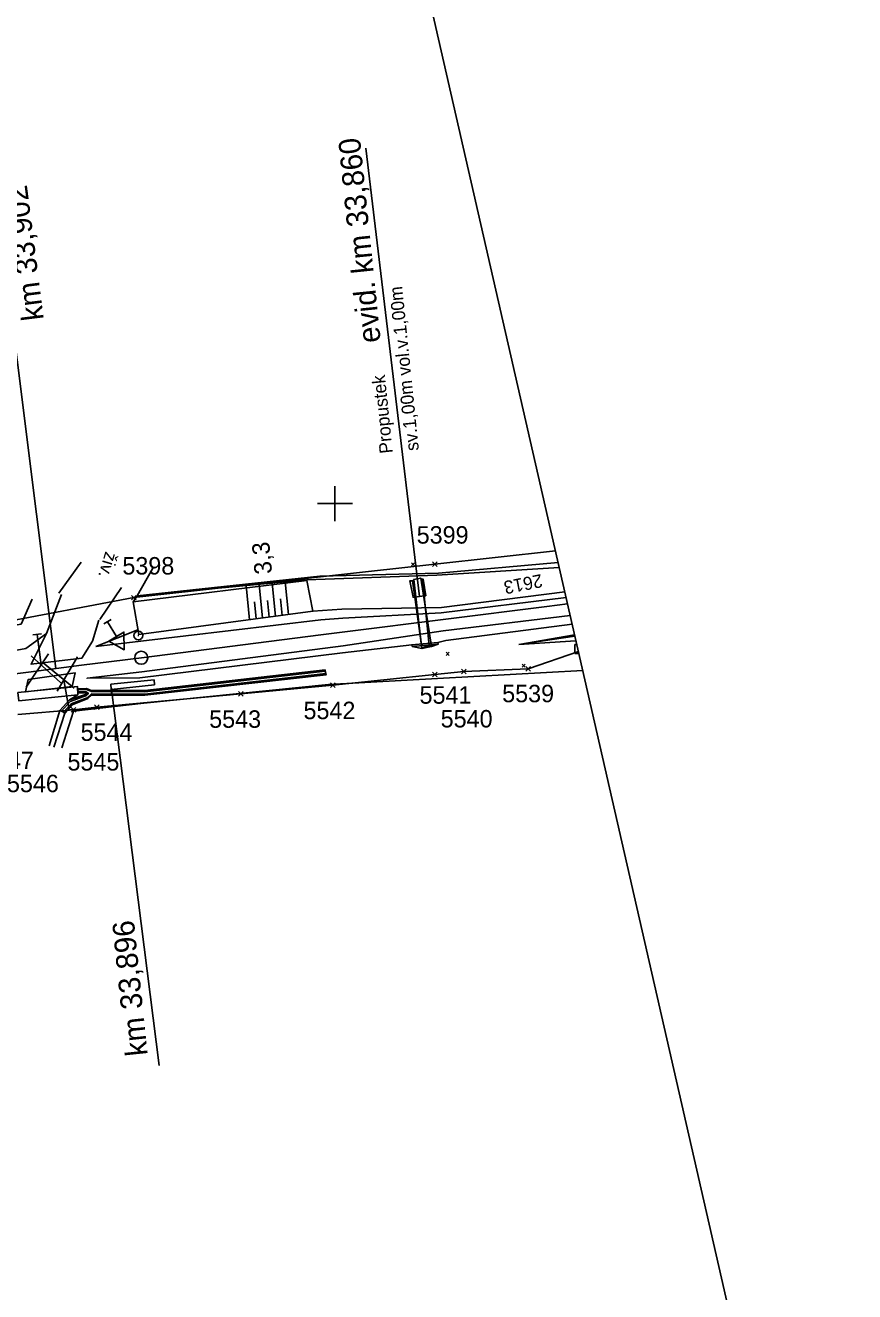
# Model space of a CAD drawing. Extents: x -805730 to -804640, y -1150889 to -1150366.
# Drawn here: x -804735.5 to -804640.4, y -1150590.3 to -1150445.2 of the extents above; entities that cross this region are included whole.
import ezdxf

# ---------------------------------------------------------------- set-up
doc = ezdxf.new("R2010")
doc.units = 0
for name, color, linetype in [('0381KM032-037P - Vrstva 1', 7, 'Continuous'), ('0381KM032-037P - Vrstva 13', 7, 'Continuous'), ('0381KM032-037P - Vrstva 17', 7, 'Continuous'), ('0381KM032-037P - Vrstva 19', 7, 'Continuous'), ('0381KM032-037P - Vrstva 25', 7, 'Continuous'), ('0381KM032-037P - Vrstva 4', 7, 'Continuous'), ('0381KM032-037P - Vrstva 43', 7, 'Continuous'), ('0381KM032-037P - Vrstva 48', 7, 'Continuous'), ('0381KM032-037P - Vrstva 49', 7, 'Continuous'), ('0381KM032-037P - Vrstva 51', 7, 'Continuous'), ('0381KM032-037P - Vrstva 57', 7, 'Continuous'), ('0381KM032-037P - Vrstva 7', 7, 'Continuous'), ('0381KM032-037P - Vrstva 9', 7, 'Continuous'), ('formát', 7, 'Continuous'), ('krizky_1000 - Vrstva 1', 7, 'Continuous'), ('szdc - hran DP', 7, 'Continuous'), ('szdc - szdc_cislo', 7, 'Continuous'), ('szdc - szdc_krizek', 7, 'Continuous')]:
    doc.layers.add(name, color=color, linetype=linetype)

msp = doc.modelspace()

# ---------------------------------------------------------------- linework, layer by layer
at = {"layer": '0381KM032-037P - Vrstva 1'}
msp.add_lwpolyline([(-804673.35, -1150511.49), (-804675.7, -1150511.78), (-804698.85, -1150514.71), (-804701.61, -1150515.06), (-804722.18, -1150517.67), (-804729.05, -1150518.54), (-804735.1, -1150519.31), (-804744.56, -1150520.5), (-804767.65, -1150523.46), (-804791, -1150526.42)], dxfattribs=at)
at = {"layer": '0381KM032-037P - Vrstva 13'}
for points in [[(-804703.22, -1150508.8), (-804723.12, -1150511.26), (-804722.46, -1150514.99), (-804702.53, -1150512.35), (-804703.22, -1150508.8)], [(-804732.2, -1150527.92), (-804730.97, -1150524.01), (-804730.13, -1150523.06), (-804728.33, -1150522.36), (-804727.9, -1150521.95), (-804721.78, -1150521.96), (-804701.01, -1150519.63), (-804701.03, -1150519.46), (-804701.1, -1150519.22), (-804701.1, -1150519.05)], [(-804729.45, -1150521.32), (-804728.46, -1150521.31), (-804727.91, -1150521.54), (-804721.8, -1150521.59), (-804701.1, -1150519.22)], [(-804729.38, -1150521.22), (-804728.48, -1150521.2), (-804727.92, -1150521.41), (-804721.8, -1150521.43), (-804701.1, -1150519.05)], [(-804731.12, -1150523.92), (-804730.21, -1150522.94), (-804728.39, -1150522.25), (-804727.91, -1150521.81), (-804721.79, -1150521.85), (-804701.03, -1150519.46)], [(-804732.74, -1150527.78), (-804731.51, -1150523.73), (-804730.41, -1150522.51), (-804728.49, -1150521.85), (-804728.25, -1150521.76), (-804728.53, -1150521.71), (-804729.44, -1150521.68)], [(-804731.32, -1150523.78), (-804730.35, -1150522.68), (-804728.48, -1150521.99), (-804728.25, -1150521.76), (-804728.5, -1150521.58), (-804729.42, -1150521.57)], [(-804729.38, -1150521.22), (-804729.45, -1150521.32), (-804729.42, -1150521.57), (-804729.44, -1150521.68)], [(-804731.51, -1150523.73), (-804731.32, -1150523.78), (-804731.12, -1150523.92), (-804730.97, -1150524.01)]]:
    msp.add_lwpolyline(points, dxfattribs=at)
at = {"layer": '0381KM032-037P - Vrstva 17'}
for p, q in [((-804731.66, -1150510.27), (-804729.1, -1150506.73)), ((-804726.96, -1150513.28), (-804724.46, -1150509.62))]:
    msp.add_line(p, q, dxfattribs=at)
for points in [[(-804674.43, -1150506.74), (-804688.14, -1150507.97), (-804701.71, -1150508.32), (-804722.68, -1150510.59), (-804720.85, -1150507.4)], [(-804734.71, -1150510.96), (-804735.96, -1150513.84), (-804741.77, -1150514.83), (-804760.36, -1150517.2), (-804795.4, -1150521.06), (-804816.51, -1150523.78), (-804835.4, -1150526.88), (-804850, -1150530.66), (-804863.08, -1150534.36), (-804866.23, -1150530.55), (-804868.05, -1150528.28)], [(-804731.29, -1150527.98), (-804729.95, -1150523.81), (-804721.9, -1150522.89), (-804700.75, -1150520.73), (-804671.6, -1150519.14)]]:
    msp.add_lwpolyline(points, dxfattribs=at)
at = {"layer": '0381KM032-037P - Vrstva 19'}
for p, q in [((-804690.3, -1150510.66), (-804696.47, -1150459.27)), ((-804690.02, -1150516.61), (-804690.96, -1150508.7)), ((-804688.92, -1150516.37), (-804690.16, -1150508.54)), ((-804690.09, -1150516.25), (-804690.83, -1150510.72)), ((-804689.77, -1150510.59), (-804689.19, -1150516.28)), ((-804690.02, -1150516.61), (-804688.92, -1150516.37))]:
    msp.add_line(p, q, dxfattribs=at)
for points in [[(-804689.58, -1150510.57), (-804689.77, -1150510.59), (-804690.83, -1150510.72), (-804691.04, -1150510.74), (-804691.4, -1150508.85), (-804691.12, -1150508.86), (-804690.83, -1150510.72)], [(-804691.12, -1150508.86), (-804690.96, -1150508.7), (-804690.59, -1150508.62), (-804690.16, -1150508.54), (-804690.08, -1150508.63)], [(-804689.58, -1150510.57), (-804689.88, -1150508.68), (-804690.08, -1150508.63), (-804689.77, -1150510.59)], [(-804688.16, -1150516.11), (-804688.92, -1150516.37), (-804689.19, -1150516.28), (-804690.09, -1150516.25), (-804690.02, -1150516.61), (-804691.14, -1150516.38)]]:
    msp.add_lwpolyline(points, dxfattribs=at)
msp.add_lwpolyline([(-804688.22, -1150515.92), (-804688.16, -1150516.11), (-804691.14, -1150516.38), (-804691.19, -1150516.18)], close=True, dxfattribs=at)
at = {"layer": '0381KM032-037P - Vrstva 25'}
for points in [[(-804672.5, -1150517.17), (-804672.5, -1150516.17), (-804672.27, -1150516.17)], [(-804672.05, -1150517.17), (-804672.5, -1150517.17)]]:
    msp.add_lwpolyline(points, dxfattribs=at)
at = {"layer": '0381KM032-037P - Vrstva 4'}
for p, q in [((-804738.68, -1150465.82), (-804731.99, -1150518.9)), ((-804699.22, -1150512.12), (-804702.53, -1150512.35)), ((-804733.62, -1150514.94), (-804734.61, -1150515.06)), ((-804734.11, -1150515), (-804733.68, -1150518.47)), ((-804691.19, -1150516.18), (-804699.14, -1150517.12)), ((-804688.22, -1150515.92), (-804691.19, -1150516.18)), ((-804732.83, -1150517.21), (-804735.37, -1150521.05)), ((-804731.4, -1150520.55), (-804734.81, -1150517.46)), ((-804731.84, -1150521.52), (-804729.49, -1150517.55)), ((-804729.05, -1150518.54), (-804735.1, -1150519.31)), ((-804733.43, -1150518.25), (-804729.87, -1150521.17)), ((-804730.44, -1150523.66), (-804731.05, -1150520.21)), ((-804730.93, -1150523.75), (-804729.95, -1150523.57))]:
    msp.add_line(p, q, dxfattribs=at)
for points in [[(-804673.66, -1150510.13), (-804687.8, -1150511.91), (-804699.22, -1150512.12)], [(-804673.51, -1150510.75), (-804687.82, -1150512.54), (-804699.1, -1150513.12)], [(-804699.1, -1150513.12), (-804701.6, -1150513.32), (-804727.4, -1150516.37)], [(-804702.53, -1150512.35), (-804722.46, -1150514.99), (-804722.57, -1150514.49)], [(-804673.03, -1150512.84), (-804687.61, -1150514.59), (-804699.07, -1150516.32)], [(-804722.57, -1150514.49), (-804727.4, -1150516.37)], [(-804672.81, -1150513.82), (-804687.3, -1150515.71), (-804688.22, -1150515.92)], [(-804699.07, -1150516.32), (-804722.12, -1150519.29), (-804728.4, -1150520.02), (-804722.36, -1150519.97), (-804699.14, -1150517.12)]]:
    msp.add_lwpolyline(points, dxfattribs=at)
at = {"layer": '0381KM032-037P - Vrstva 43'}
msp.add_lwpolyline([(-804736.33, -1150521.65), (-804729.5, -1150520.98), (-804729.45, -1150521.92), (-804736.22, -1150522.62)], close=True, dxfattribs=at)
at = {"layer": '0381KM032-037P - Vrstva 48'}
for p, q in [((-804706.81, -1150512.92), (-804707.19, -1150509.11)), ((-804705.32, -1150512.72), (-804705.69, -1150508.97)), ((-804709.78, -1150513.31), (-804710.17, -1150509.4)), ((-804708.29, -1150513.12), (-804708.68, -1150509.26)), ((-804709.04, -1150513.21), (-804709.23, -1150511.27)), ((-804707.55, -1150513.02), (-804707.74, -1150511.1)), ((-804706.06, -1150512.82), (-804706.25, -1150510.93))]:
    msp.add_line(p, q, dxfattribs=at)
at = {"layer": '0381KM032-037P - Vrstva 49'}
for p, q in [((-804690.87, -1150506.79), (-804691.22, -1150507.14)), ((-804691.22, -1150506.79), (-804690.87, -1150507.14)), ((-804686.9, -1150517.05), (-804687.25, -1150517.41)), ((-804687.25, -1150517.05), (-804686.9, -1150517.41)), ((-804678.19, -1150518.41), (-804678.54, -1150518.76)), ((-804678.54, -1150518.41), (-804678.19, -1150518.76))]:
    msp.add_line(p, q, dxfattribs=at)
for points in [[(-804674.3, -1150507.31), (-804688.31, -1150508.22), (-804703.24, -1150508.74), (-804722.68, -1150510.59)], [(-804731.33, -1150510.42), (-804733.06, -1150514.89), (-804735.43, -1150516.61), (-804744.9, -1150518.34), (-804767.83, -1150521.26), (-804795.17, -1150523.55), (-804815.65, -1150527.19), (-804834.76, -1150530), (-804839.27, -1150531.31), (-804861.98, -1150536.58)], [(-804673.66, -1150510.13), (-804687.8, -1150511.91), (-804699.22, -1150512.12)], [(-804722.46, -1150514.99), (-804723.12, -1150511.26), (-804722.68, -1150510.59)], [(-804699.22, -1150512.12), (-804702.53, -1150512.35), (-804722.46, -1150514.99)], [(-804690.02, -1150516.61), (-804688.92, -1150516.37), (-804689.47, -1150516.35), (-804690.02, -1150516.61)], [(-804672.53, -1150515.06), (-804678.92, -1150516.15)], [(-804672.49, -1150515.21), (-804675.11, -1150515.57), (-804678.92, -1150516.15)], [(-804672.38, -1150515.72), (-804678.92, -1150516.15)]]:
    msp.add_lwpolyline(points, dxfattribs=at)
at = {"layer": '0381KM032-037P - Vrstva 51'}
msp.add_line((-804725.64, -1150513.28), (-804726.5, -1150513.8), dxfattribs=at)
for points in [[(-804727.06, -1150513.38), (-804727.78, -1150515.77), (-804729, -1150517.7), (-804734.83, -1150518.42), (-804733.06, -1150514.89), (-804731.33, -1150510.42)], [(-804726.07, -1150513.54), (-804725.04, -1150515.25), (-804725.9, -1150515.77), (-804724.14, -1150516.75), (-804724.18, -1150514.73), (-804725.04, -1150515.25)], [(-804729.45, -1150521.92), (-804730.41, -1150522.51), (-804731.51, -1150523.73), (-804732.74, -1150527.78)]]:
    msp.add_lwpolyline(points, dxfattribs=at)
msp.add_lwpolyline([(-804730.11, -1150520.97), (-804729.76, -1150519.41), (-804735.16, -1150520.17), (-804735.48, -1150521.58)], close=True, dxfattribs=at)
at = {"layer": '0381KM032-037P - Vrstva 7'}
msp.add_line((-804722.48, -1150515.11), (-804722.58, -1150515.12), dxfattribs=at)
for centre, radius in [((-804722.53, -1150515.12), 0.5), ((-804722.2, -1150517.67), 0.75)]:
    msp.add_circle(centre, radius, dxfattribs=at)
at = {"layer": '0381KM032-037P - Vrstva 9'}
for p, q in [((-804720.72, -1150520.2), (-804725.69, -1150520.71)), ((-804725.69, -1150520.71), (-804725.63, -1150521.31)), ((-804720.66, -1150520.79), (-804720.72, -1150520.2)), ((-804725.66, -1150521.01), (-804720.15, -1150564.39)), ((-804725.63, -1150521.31), (-804720.66, -1150520.79)), ((-804725.63, -1150521.31), (-804725.57, -1150521.9))]:
    msp.add_line(p, q, dxfattribs=at)
at = {"layer": 'formát'}
msp.add_line((-804706.6, -1150365.97), (-804640.43, -1150655.5), dxfattribs=at)
at = {"layer": 'krizky_1000 - Vrstva 1'}
for points in [[(-804700, -1150498), (-804700, -1150502)], [(-804702, -1150500), (-804698, -1150500)]]:
    msp.add_lwpolyline(points, dxfattribs=at)
at = {"layer": 'szdc - hran DP'}
for p, q in [((-804688.55, -1150506.95), (-804674.73, -1150505.41)), ((-804723.03, -1150510.78), (-804688.55, -1150506.95)), ((-804747.72, -1150515.43), (-804723.03, -1150510.78)), ((-804672.1, -1150516.95), (-804677.85, -1150518.93)), ((-804685.22, -1150519.25), (-804688.56, -1150519.6)), ((-804677.85, -1150518.93), (-804685.22, -1150519.25)), ((-804688.56, -1150519.6), (-804700.23, -1150520.83)), ((-804710.79, -1150521.81), (-804727.28, -1150523.34)), ((-804700.23, -1150520.83), (-804710.79, -1150521.81)), ((-804729.97, -1150523.63), (-804736.36, -1150524.18)), ((-804727.28, -1150523.34), (-804729.97, -1150523.63))]:
    msp.add_line(p, q, dxfattribs=at)
at = {"layer": 'szdc - szdc_krizek'}
for p, q in [((-804688.29, -1150507.22), (-804688.82, -1150506.69)), ((-804688.82, -1150507.22), (-804688.29, -1150506.69)), ((-804722.77, -1150511.04), (-804723.3, -1150510.52)), ((-804723.3, -1150511.04), (-804722.77, -1150510.52)), ((-804684.96, -1150519.52), (-804685.49, -1150518.99)), ((-804685.49, -1150519.52), (-804684.96, -1150518.99)), ((-804677.58, -1150519.2), (-804678.12, -1150518.67)), ((-804678.12, -1150519.2), (-804677.58, -1150518.67)), ((-804699.96, -1150521.09), (-804700.5, -1150520.56)), ((-804700.5, -1150521.09), (-804699.96, -1150520.56)), ((-804688.3, -1150519.86), (-804688.83, -1150519.33)), ((-804688.83, -1150519.86), (-804688.3, -1150519.33)), ((-804710.53, -1150522.07), (-804711.06, -1150521.54)), ((-804711.06, -1150522.07), (-804710.53, -1150521.54)), ((-804729.71, -1150523.9), (-804730.24, -1150523.36)), ((-804730.24, -1150523.9), (-804729.71, -1150523.36)), ((-804727.02, -1150523.6), (-804727.55, -1150523.07)), ((-804727.55, -1150523.6), (-804727.02, -1150523.07))]:
    msp.add_line(p, q, dxfattribs=at)

# ---------------------------------------------------------------- texts
at = {"layer": '0381KM032-037P - Vrstva 19'}
for s, height, p in [('evid. km 33,860', 2.5, (-804694.74, -1150481.46)), ('sv.1,00m vol.v.1,00m', 1.5, (-804690.37, -1150493.89)), ('Propustek', 1.5, (-804693.36, -1150494.19))]:
    msp.add_text(s, height=height, rotation=95.8316, dxfattribs=at).set_placement(p)
at = {"layer": '0381KM032-037P - Vrstva 4'}
msp.add_text('km 33,902', height=2.5, rotation=97.1938, dxfattribs=at).set_placement((-804733.36, -1150478.88))
at = {"layer": '0381KM032-037P - Vrstva 48'}
msp.add_text('3,3', height=2, rotation=95.4373, dxfattribs=at).set_placement((-804707.19, -1150508.01))
at = {"layer": '0381KM032-037P - Vrstva 51'}
msp.add_text('živ.', height=1.5, rotation=253.3622, dxfattribs=at).set_placement((-804726.29, -1150505.42))
at = {"layer": '0381KM032-037P - Vrstva 57'}
msp.add_text('2613', height=1.5, rotation=191.1139, dxfattribs=at).set_placement((-804676.37, -1150508.07))
at = {"layer": '0381KM032-037P - Vrstva 9'}
msp.add_text('km 33,896', height=2.5, rotation=95.8904, dxfattribs=at).set_placement((-804721.45, -1150563.2))
at = {"layer": 'szdc - szdc_cislo'}
for s, p in [('5399', (-804690.63, -1150504.59)), ('5398', (-804724.36, -1150508.13)), ('5539', (-804680.83, -1150522.77)), ('5541', (-804690.3, -1150522.94)), ('5542', (-804703.6, -1150524.71)), ('5540', (-804687.88, -1150525.66)), ('5543', (-804714.41, -1150525.7)), ('5544', (-804729.15, -1150527.2)), ('5547', (-804740.45, -1150530.44)), ('5545', (-804730.65, -1150530.6)), ('5546', (-804737.59, -1150533.08))]:
    msp.add_text(s, height=2, dxfattribs=at).set_placement(p)

doc.saveas('drawing.dxf')
